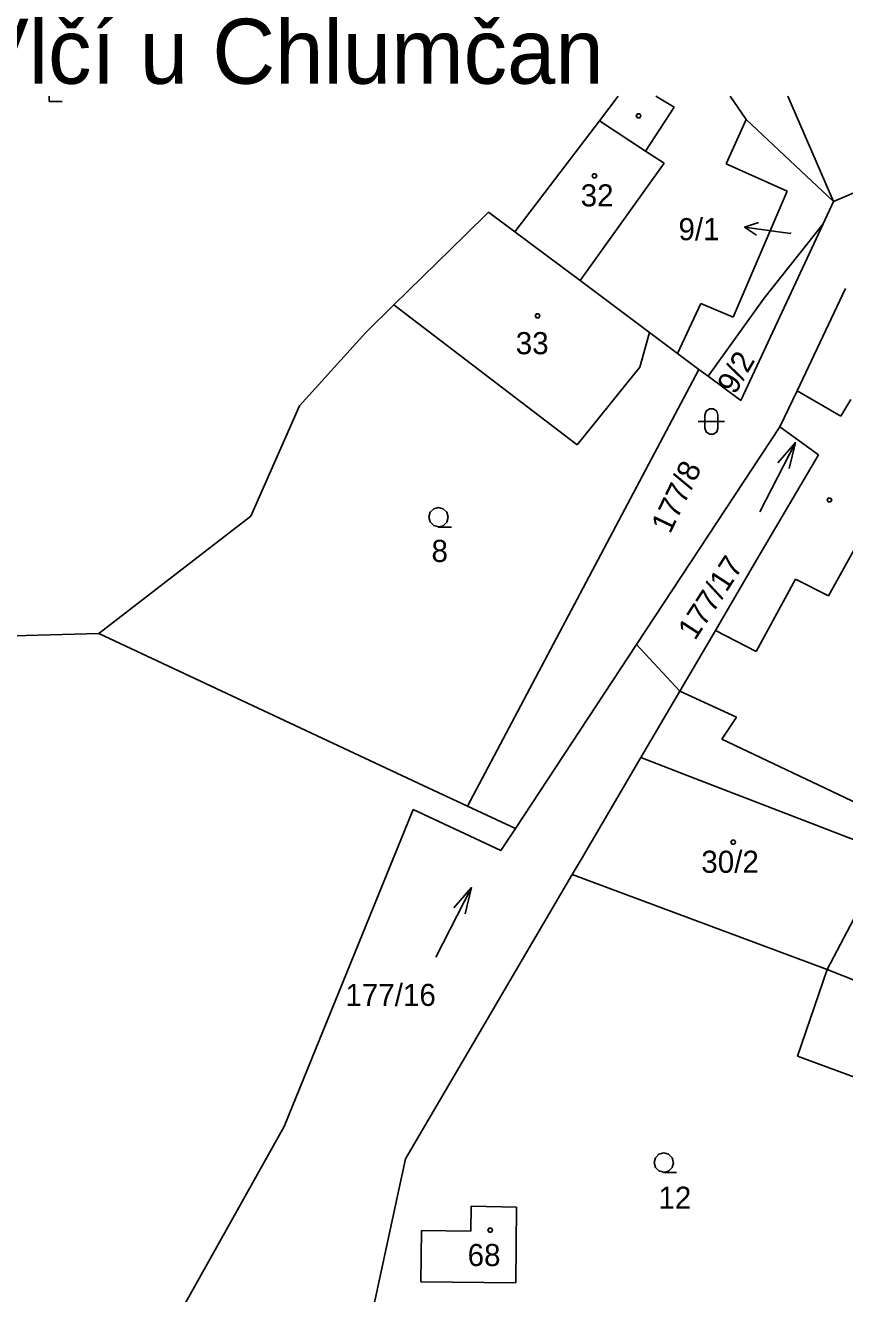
# Model space of a CAD drawing. Extents: x -779723 to -777378, y -1011169 to -1009297.
# Drawn here: x -779247 to -779184, y -1010377.2 to -1010279.6 of the extents above; entities that cross this region are included whole.
import ezdxf

# ---------------------------------------------------------------- set-up
doc = ezdxf.new("R2010")
doc.units = 0
for name, color, linetype in [('Default', 7, 'Continuous'), ('KN_HRANICE', 7, 'Continuous'), ('KN_KULTURY', 7, 'Continuous'), ('KN_PARCELY', 7, 'Continuous'), ('KN_SLUCKY', 7, 'Continuous'), ('LEGENDA', 7, 'Continuous')]:
    doc.layers.add(name, color=color, linetype=linetype)

# ---------------------------------------------------------------- blocks, each defined once
blk = doc.blocks.new('304')
at = {"layer": 'Default'}
blk.add_lwpolyline([(0, 0), (-0.38, 0.1), (-0.65, 0.37), (-0.75, 0.74), (-0.65, 1.11), (-0.38, 1.38), (-0.01, 1.48), (0.36, 1.38), (0.63, 1.11), (0.73, 0.73), (0.63, 0.35), (0.36, 0.08), (-0.02, -0.02), (0.98, -0.02)], dxfattribs=at)
blk = doc.blocks.new('316')
at = {"layer": 'Default'}
for points in [[(-0.5, 1.5), (-0.4, 1.79), (-0.15, 1.97), (0.16, 1.97), (0.41, 1.79), (0.51, 1.5), (0.51, 0.5), (0.41, 0.21), (0.16, 0.03), (-0.15, 0.03), (-0.4, 0.21), (-0.5, 0.5), (-0.5, 1.5)], [(-1, 1), (0.27, 1), (1, 1)]]:
    blk.add_lwpolyline(points, dxfattribs=at)
blk = doc.blocks.new('NAHRADNI_SYMBOL')
at = {"layer": 'Default'}
blk.add_lwpolyline([(0.09, 0.15), (0.18, 0), (0.09, -0.15), (-0.09, -0.15), (-0.18, 0), (-0.09, 0.15), (0.09, 0.15)], dxfattribs=at)
blk = doc.blocks.new('802')
at = {"layer": 'Default'}
blk.add_line((-3, 0), (3, 0), dxfattribs=at)
blk.add_lwpolyline([(1, 0.5), (3, 0), (1, -0.5)], dxfattribs=at)
blk = doc.blocks.new('10292')
at = {"layer": 'Default'}
blk.add_line((0, 3), (0, 0), dxfattribs=at)
blk.add_lwpolyline([(-0.5, 2), (0, 3), (0.5, 2)], dxfattribs=at)
blk = doc.blocks.new('402')
at = {"layer": 'Default'}
blk.add_lwpolyline([(0.09, 0.15), (0.18, 0), (0.09, -0.15), (-0.09, -0.15), (-0.18, 0), (-0.09, 0.15), (0.09, 0.15)], dxfattribs=at)

msp = doc.modelspace()

# ---------------------------------------------------------------- linework, layer by layer
at = {"layer": 'KN_HRANICE'}
for p, q in [((-779201.402, -1010285.087), (-779202.85, -1010286.98)), ((-779191.55, -1010286.87), (-779192.804, -1010285.087)), ((-779188.347, -1010285.087), (-779184.85, -1010293.19)), ((-779193.1, -1010290.28), (-779191.55, -1010286.87)), ((-779191.55, -1010286.87), (-779184.85, -1010293.19)), ((-779202.85, -1010286.98), (-779209.36, -1010295.51)), ((-779184.85, -1010293.19), (-779176.23, -1010289.47)), ((-779188.41, -1010292.39), (-779193.1, -1010290.28)), ((-779192.55, -1010302.07), (-779188.41, -1010292.39)), ((-779184.85, -1010293.19), (-779185.64, -1010294.9)), ((-779211.37, -1010294.01), (-779213.17, -1010295.76)), ((-779211.37, -1010294.01), (-779209.36, -1010295.51)), ((-779209.36, -1010295.51), (-779204.33, -1010299.27)), ((-779185.64, -1010294.9), (-779191.98, -1010308.5)), ((-779213.17, -1010295.76), (-779218.66, -1010301.14)), ((-779204.33, -1010299.27), (-779198.99, -1010303.26)), ((-779187.65, -1010307.74), (-779183.92, -1010299.88)), ((-779218.66, -1010301.14), (-779220.82, -1010303.25)), ((-779218.66, -1010301.14), (-779215.5, -1010303.55)), ((-779196.83, -1010304.88), (-779195.06, -1010301.02)), ((-779195.06, -1010301.02), (-779192.55, -1010302.07)), ((-779225.92, -1010308.91), (-779220.82, -1010303.25)), ((-779199.75, -1010305.93), (-779198.99, -1010303.26)), ((-779198.99, -1010303.26), (-779196.83, -1010304.88)), ((-779215.5, -1010303.55), (-779204.57, -1010311.9)), ((-779196.83, -1010304.88), (-779195.2, -1010306.1)), ((-779212.98, -1010339.7), (-779195.2, -1010306.1)), ((-779204.57, -1010311.9), (-779199.75, -1010305.93)), ((-779195.2, -1010306.1), (-779194.49, -1010306.63)), ((-779194.49, -1010306.63), (-779191.98, -1010308.5)), ((-779188.97, -1010310.51), (-779187.65, -1010307.74)), ((-779187.65, -1010307.74), (-779184.27, -1010309.7)), ((-779225.92, -1010308.91), (-779229.64, -1010317.38)), ((-779184.27, -1010309.7), (-779183.51, -1010308.4)), ((-779200, -1010327.27), (-779188.97, -1010310.51)), ((-779188.97, -1010310.51), (-779186, -1010312.66)), ((-779190.73, -1010320.73), (-779186, -1010312.66)), ((-779241.34, -1010326.4), (-779229.64, -1010317.38)), ((-779193.92, -1010326.17), (-779190.73, -1010320.73)), ((-779248.83, -1010326.61), (-779241.34, -1010326.4)), ((-779216.41, -1010338.1), (-779241.34, -1010326.4)), ((-779196.66, -1010330.84), (-779193.92, -1010326.17)), ((-779209.31, -1010341.42), (-779200, -1010327.27)), ((-779200, -1010327.27), (-779196.66, -1010330.84)), ((-779199.66, -1010335.95), (-779196.66, -1010330.84)), ((-779196.66, -1010330.84), (-779192.3, -1010332.84)), ((-779193.43, -1010334.55), (-779192.3, -1010332.84)), ((-779182.94, -1010339.51), (-779193.43, -1010334.55)), ((-779204.25, -1010343.79), (-779199.66, -1010335.95)), ((-779216.41, -1010338.1), (-779212.98, -1010339.7)), ((-779227.1, -1010364.33), (-779217.17, -1010339.95)), ((-779212.98, -1010339.7), (-779209.31, -1010341.42)), ((-779204.93, -1010344.94), (-779204.25, -1010343.79)), ((-779217.76, -1010366.81), (-779204.93, -1010344.94)), ((-779185.33, -1010352.25), (-779204.93, -1010344.94)), ((-779185.33, -1010352.25), (-779187.61, -1010358.93)), ((-779187.61, -1010358.93), (-779174.51, -1010363.75)), ((-779237.61, -1010383.13), (-779227.1, -1010364.33)), ((-779222.02, -1010386.49), (-779217.76, -1010366.81)), ((-779212.71, -1010370.47), (-779212.73, -1010372.38)), ((-779212.71, -1010370.47), (-779209.21, -1010370.54)), ((-779209.21, -1010370.54), (-779209.28, -1010376.35)), ((-779216.52, -1010372.33), (-779216.59, -1010376.27)), ((-779216.52, -1010372.33), (-779212.73, -1010372.38)), ((-779216.59, -1010376.27), (-779209.28, -1010376.35))]:
    msp.add_line(p, q, dxfattribs=at)
for points in [[(-779185.64, -1010294.9), (-779190.18, -1010300.61), (-779194.49, -1010306.63)], [(-779217.17, -1010339.95), (-779210.43, -1010343.11), (-779209.31, -1010341.42)]]:
    msp.add_lwpolyline(points, dxfattribs=at)
at = {"layer": 'KN_KULTURY'}
msp.add_lwpolyline([(-779245.15, -1010285.087), (-779245.15, -1010285.49), (-779244.15, -1010285.49)], dxfattribs=at)
at = {"layer": 'KN_PARCELY'}
msp.add_line((-779188.12, -1010295.64), (-779188.71, -1010295.56), dxfattribs=at)
at = {"layer": 'KN_SLUCKY'}
for p, q in [((-779197.09, -1010285.92), (-779198.515, -1010285.087)), ((-779199.3, -1010289.31), (-779197.09, -1010285.92)), ((-779202.85, -1010286.98), (-779199.3, -1010289.31)), ((-779199.3, -1010289.31), (-779197.88, -1010290.24)), ((-779204.33, -1010299.27), (-779197.88, -1010290.24)), ((-779185.22, -1010323.51), (-779179.44, -1010313.05)), ((-779190.79, -1010327.79), (-779187.78, -1010322.22)), ((-779185.22, -1010323.51), (-779187.78, -1010322.22)), ((-779193.92, -1010326.17), (-779190.79, -1010327.79)), ((-779195.44, -1010337.58), (-779199.66, -1010335.95)), ((-779195.44, -1010337.58), (-779184.06, -1010341.97)), ((-779184.06, -1010341.97), (-779180.63, -1010343.29)), ((-779185.33, -1010352.25), (-779180.63, -1010343.29)), ((-779185.33, -1010352.25), (-779172.96, -1010357.18))]:
    msp.add_line(p, q, dxfattribs=at)

# ---------------------------------------------------------------- block references
at = {"layer": 'KN_KULTURY'}
for name, p in [('402', (-779199.83, -1010286.59)), ('402', (-779203.23, -1010291.21)), ('NAHRADNI_SYMBOL', (-779207.6, -1010301.97)), ('316', (-779194.24, -1010311.11)), ('402', (-779185.16, -1010316.14)), ('304', (-779215.21, -1010318.2)), ('402', (-779192.55, -1010342.47)), ('304', (-779197.89, -1010367.85)), ('402', (-779211.24, -1010372.3))]:
    msp.add_blockref(name, p, dxfattribs=at)
at = {"layer": 'KN_KULTURY', "rotation": 62.796174}
for p in [(-779189.15, -1010314.39), (-779214.06, -1010348.63)]:
    msp.add_blockref('802', p, dxfattribs=at)
at = {"layer": 'KN_PARCELY', "rotation": 82.162148}
msp.add_blockref('10292', (-779188.71, -1010295.56), dxfattribs=at)

# ---------------------------------------------------------------- texts
at = {"layer": 'KN_PARCELY'}
for s, height, p in [('32', 1.7, (-779204.29, -1010293.56)), ('9/1', 1.7, (-779196.767, -1010296.16)), ('9/1', 0.1, (-779188.253, -1010295.64)), ('33', 1.7, (-779209.28, -1010304.93)), ('8', 1.7, (-779215.76, -1010320.91)), ('30/2', 1.7, (-779195.01, -1010344.82)), ('177/16', 1.7, (-779222.38, -1010355.06)), ('12', 1.7, (-779198.31, -1010370.66)), ('68', 1.7, (-779212.98, -1010375.07))]:
    msp.add_text(s, height=height, dxfattribs=at).set_placement(p)
for s, rotation, p in [('9/2', 59.874, (-779192.42, -1010308.101)), ('177/8', 64.4, (-779197.41, -1010318.81)), ('177/17', 56.952, (-779195.499, -1010327.011))]:
    msp.add_text(s, height=1.7, rotation=rotation, dxfattribs=at).set_placement(p)
at = {"layer": 'LEGENDA'}
msp.add_text('katastrální mapa Vlčí u Chlumčan', height=5, dxfattribs=at).set_placement((-779302.478, -1010284.125))

doc.saveas('drawing.dxf')
